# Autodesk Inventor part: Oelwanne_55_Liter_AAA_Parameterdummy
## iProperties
Created: 2005-05
Part Number: Oelwanne_55_Liter_AAA_Parameterdummy
Material: Stahl (schweißbar)
Document SubType Name: Modeling
Designer: Mario Wipf
Manufacturer: Standard
Standards Organization: Custom
gesamtbreite: 470.000 mm
materialstaerke_deckel: 2.000 mm
materialstaerke_wanne: 2.000 mm
materialstaerke_seitenbleche: 2.000 mm
abstand_unterkante_wanne_bis_auflageflaeche: 60.000 mm
gesamthoehe: 370.000 mm
gesamtlaenge: 600.000 mm
stegbreite: 20.000 mm
strebe_materialstaerke: 3.000 mm
Volumen: 84.987 l
abstand_verstrebungen_von_aussen: 60.000 mm
Author: Mario Wipf
